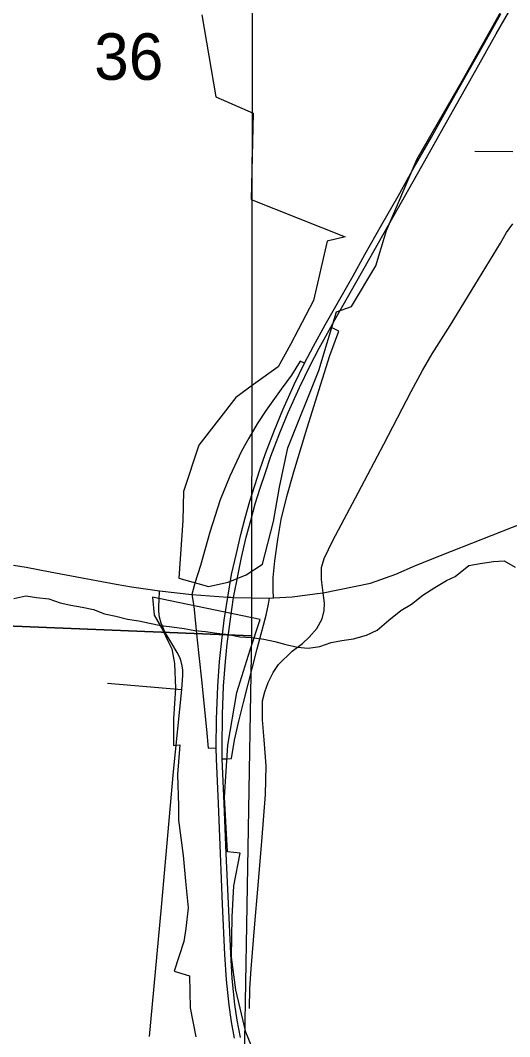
# Model space of a CAD drawing. Extents: x 2.1 to 8.9, y 14.1 to 20.9.
# Drawn here: x 7.249 to 7.689, y 17.687 to 18.602 of the extents above; entities that cross this region are included whole.
import ezdxf

# ---------------------------------------------------------------- set-up
doc = ezdxf.new("R2010")
doc.units = 0
for name, color, linetype in [('GM_X_County_Road_Text', 7, 'Continuous'), ('GM_X_Interchange_Ramps', 7, 'Continuous'), ('GM_X_Rail_Line_Text', 7, 'Continuous'), ('GM_X_State_Shield', 7, 'Continuous'), ('GM_X_Township_Road', 7, 'Continuous'), ('GM_X_Unincorporated', 7, 'Continuous'), ('GM_X_Unincorporated_Text', 7, 'Continuous'), ('TX_P_Misc', 7, 'Continuous')]:
    doc.layers.add(name, color=color, linetype=linetype)

msp = doc.modelspace()

# ---------------------------------------------------------------- linework, layer by layer
at = {"layer": 'GM_X_Interchange_Ramps'}
for p, q in [((7.45846, 19.10807), (7.45701, 18.04776)), ((7.45701, 18.04776), (6.44653, 18.08952)), ((6.44653, 18.08952), (7.45701, 18.04776)), ((7.45701, 18.04776), (7.44097, 17.09977))]:
    msp.add_line(p, q, dxfattribs=at)
at = {"layer": 'GM_X_Rail_Line_Text'}
for p, q in [((7.67745, 18.58945), (7.70305, 18.63467)), ((7.66704, 18.58183), (7.6815, 18.60746)), ((7.65903, 18.55671), (7.67745, 18.58945)), ((7.65216, 18.55536), (7.66704, 18.58183)), ((7.63273, 18.51016), (7.65903, 18.55671)), ((7.63373, 18.52289), (7.65216, 18.55536)), ((7.61896, 18.49652), (7.63373, 18.52289)), ((7.6103, 18.47046), (7.63273, 18.51016)), ((7.60356, 18.46943), (7.61896, 18.49652)), ((7.58426, 18.42437), (7.6103, 18.47046)), ((7.58899, 18.44354), (7.60356, 18.46943)), ((7.57453, 18.41806), (7.58899, 18.44354)), ((7.55834, 18.3785), (7.58426, 18.42437)), ((7.55918, 18.39091), (7.57453, 18.41806)), ((7.54848, 18.37186), (7.55918, 18.39091)), ((7.53219, 18.33221), (7.55834, 18.3785)), ((7.53303, 18.34451), (7.54848, 18.37186)), ((7.52342, 18.32764), (7.53303, 18.34451)), ((7.52849, 18.32567), (7.53219, 18.33221)), ((7.51285, 18.30852), (7.52342, 18.32764)), ((7.51792, 18.30655), (7.52849, 18.32567)), ((7.50488, 18.29304), (7.51285, 18.30852)), ((7.50971, 18.2906), (7.51792, 18.30655)), ((7.49544, 18.27382), (7.50488, 18.29304)), ((7.50027, 18.27138), (7.50971, 18.2906)), ((7.48534, 18.25111), (7.49544, 18.27382)), ((7.49008, 18.24865), (7.50027, 18.27138)), ((7.47779, 18.23274), (7.48534, 18.25111)), ((7.48262, 18.23031), (7.49008, 18.24865)), ((7.46979, 18.21189), (7.47779, 18.23274)), ((7.47462, 18.20946), (7.48262, 18.23031)), ((7.46472, 18.1973), (7.46979, 18.21189)), ((7.46955, 18.19486), (7.47462, 18.20946)), ((7.46006, 18.18305), (7.46472, 18.1973)), ((7.46489, 18.18061), (7.46955, 18.19486)), ((7.45568, 18.16887), (7.46006, 18.18305)), ((7.46051, 18.16643), (7.46489, 18.18061)), ((7.45151, 18.15407), (7.45568, 18.16887)), ((7.45634, 18.15163), (7.46051, 18.16643)), ((7.44755, 18.13898), (7.45151, 18.15407)), ((7.45238, 18.13655), (7.45634, 18.15163)), ((7.44347, 18.1218), (7.44755, 18.13898)), ((7.44819, 18.11837), (7.45238, 18.13655)), ((7.43919, 18.10285), (7.44347, 18.1218)), ((7.44446, 18.10034), (7.44819, 18.11837)), ((7.4357, 18.08267), (7.43919, 18.10285)), ((7.44212, 18.08831), (7.44407, 18.09833)), ((7.44407, 18.09833), (7.44446, 18.10034)), ((7.43248, 18.06179), (7.4357, 18.08267)), ((7.44095, 18.0823), (7.44212, 18.08831)), ((7.43772, 18.06056), (7.44095, 18.0823)), ((7.42993, 18.04075), (7.43248, 18.06179)), ((7.43528, 18.04048), (7.43772, 18.06056)), ((7.42836, 18.02473), (7.42993, 18.04075)), ((7.43362, 18.0247), (7.43528, 18.04048)), ((7.42669, 18.00244), (7.42836, 18.02473)), ((7.43195, 18.00239), (7.43362, 18.0247)), ((7.42549, 17.97289), (7.42669, 18.00244)), ((7.43086, 17.9769), (7.43195, 18.00239)), ((7.42539, 17.94694), (7.42549, 17.97289)), ((7.43064, 17.94707), (7.43086, 17.9769)), ((7.42553, 17.93703), (7.42539, 17.94694)), ((7.43079, 17.93717), (7.43064, 17.94707)), ((7.42732, 17.89689), (7.42553, 17.93703)), ((7.43257, 17.89702), (7.43079, 17.93717)), ((7.42912, 17.85178), (7.42732, 17.89689)), ((7.43438, 17.85191), (7.43257, 17.89702)), ((7.43102, 17.80636), (7.42912, 17.85178)), ((7.43647, 17.80674), (7.43438, 17.85191)), ((7.43311, 17.76089), (7.43102, 17.80636)), ((7.43841, 17.76198), (7.43647, 17.80674)), ((7.43447, 17.73807), (7.43311, 17.76089)), ((7.43973, 17.73939), (7.43841, 17.76198)), ((7.43682, 17.71552), (7.43447, 17.73807)), ((7.4421, 17.71604), (7.43973, 17.73939)), ((7.43901, 17.70038), (7.43682, 17.71552)), ((7.44418, 17.70186), (7.4421, 17.71604)), ((7.44183, 17.68556), (7.43901, 17.70038)), ((7.4471, 17.68629), (7.44418, 17.70186))]:
    msp.add_line(p, q, dxfattribs=at)
at = {"layer": 'GM_X_State_Shield'}
for p, q in [((7.68675, 18.41067), (7.69238, 18.41859)), ((7.68112, 18.40121), (7.68675, 18.41067)), ((7.65797, 18.36327), (7.68112, 18.40121)), ((7.6358, 18.32699), (7.65797, 18.36327)), ((7.61982, 18.30155), (7.6358, 18.32699)), ((7.61113, 18.2866), (7.61982, 18.30155)), ((7.60091, 18.2677), (7.61113, 18.2866)), ((7.5761, 18.22023), (7.60091, 18.2677)), ((7.55323, 18.17658), (7.5761, 18.22023)), ((7.53036, 18.13363), (7.55323, 18.17658)), ((7.63711, 18.12395), (7.71217, 18.15371)), ((7.52237, 18.1175), (7.53036, 18.13363)), ((7.60462, 18.11105), (7.63711, 18.12395)), ((7.24297, 18.11147), (7.25412, 18.10949)), ((7.52008, 18.10916), (7.52237, 18.1175)), ((7.58701, 18.10323), (7.60462, 18.11105)), ((7.25412, 18.10949), (7.27571, 18.1055)), ((7.27571, 18.1055), (7.29975, 18.10101)), ((7.29975, 18.10101), (7.3353, 18.09434)), ((7.51994, 18.09839), (7.52008, 18.10916)), ((7.56408, 18.09525), (7.58701, 18.10323)), ((7.3353, 18.09434), (7.3492, 18.09194)), ((7.3492, 18.09194), (7.3513, 18.09165)), ((7.52161, 18.08644), (7.51994, 18.09839)), ((7.52161, 18.08644), (7.56408, 18.09525)), ((7.3513, 18.09165), (7.3618, 18.09017)), ((7.3618, 18.09017), (7.3744, 18.0884)), ((7.3744, 18.0884), (7.40347, 18.08491)), ((7.40347, 18.08491), (7.4357, 18.08267)), ((7.4357, 18.08267), (7.43832, 18.08248)), ((7.47684, 18.08184), (7.49367, 18.08284)), ((7.49367, 18.08284), (7.51662, 18.08579)), ((7.51662, 18.08579), (7.52161, 18.08644)), ((7.43832, 18.08248), (7.44095, 18.0823)), ((7.44095, 18.0823), (7.47317, 18.08162)), ((7.47317, 18.08162), (7.47684, 18.08184))]:
    msp.add_line(p, q, dxfattribs=at)
at = {"layer": 'GM_X_Township_Road'}
for p, q in [((7.64793, 18.54939), (7.68445, 18.61475)), ((7.41227, 18.60674), (7.42509, 18.53276)), ((7.60633, 18.47702), (7.64793, 18.54939)), ((7.42509, 18.53276), (7.45863, 18.51813)), ((7.45863, 18.51813), (7.45666, 18.44053)), ((7.57848, 18.41269), (7.60633, 18.47702)), ((7.45666, 18.44053), (7.54149, 18.40699)), ((7.56891, 18.38085), (7.57848, 18.41269)), ((7.52522, 18.4028), (7.51289, 18.34953)), ((7.54149, 18.40699), (7.52522, 18.4028)), ((7.54699, 18.34405), (7.56891, 18.38085)), ((7.51289, 18.34953), (7.49217, 18.31008)), ((7.51779, 18.28651), (7.5335, 18.33944)), ((7.5335, 18.33944), (7.54699, 18.34405)), ((7.49217, 18.31008), (7.48107, 18.28986)), ((7.48107, 18.28986), (7.45888, 18.27383)), ((7.48974, 18.21683), (7.51779, 18.28651)), ((7.45888, 18.27383), (7.44285, 18.26224)), ((7.44285, 18.26224), (7.40956, 18.21933)), ((7.40956, 18.21933), (7.39575, 18.17765)), ((7.48216, 18.18164), (7.48974, 18.21683)), ((7.39575, 18.17765), (7.39514, 18.15144)), ((7.47673, 18.15068), (7.48216, 18.18164)), ((7.39514, 18.15144), (7.3917, 18.09977)), ((7.46698, 18.11237), (7.47673, 18.15068)), ((7.45213, 18.10277), (7.46698, 18.11237)), ((7.43605, 18.09617), (7.45213, 18.10277)), ((7.3917, 18.09977), (7.41836, 18.09217)), ((7.41836, 18.09217), (7.43605, 18.09617)), ((7.46482, 18.06252), (7.36788, 18.08256)), ((7.36788, 18.08256), (7.36955, 18.06628)), ((7.36955, 18.06628), (7.37718, 18.05284)), ((7.45585, 18.03524), (7.46482, 18.06252)), ((7.37718, 18.05284), (7.38206, 18.04274)), ((7.38206, 18.04274), (7.38532, 18.036)), ((7.38532, 18.036), (7.38764, 18.02278)), ((7.44383, 17.99685), (7.45585, 18.03524)), ((7.38764, 18.02278), (7.38874, 18.00077)), ((7.38874, 18.00077), (7.38698, 17.97296)), ((7.43589, 17.94946), (7.44383, 17.99685)), ((7.38698, 17.97296), (7.387, 17.94902)), ((7.387, 17.94902), (7.39267, 17.94959)), ((7.39267, 17.94959), (7.3905, 17.92291)), ((7.43286, 17.90261), (7.43589, 17.94946)), ((7.3905, 17.92291), (7.39141, 17.89481)), ((7.43559, 17.85329), (7.43286, 17.90261)), ((7.39141, 17.89481), (7.39145, 17.88188)), ((7.39145, 17.88188), (7.39551, 17.85009)), ((7.39551, 17.85009), (7.39778, 17.82697)), ((7.44701, 17.85213), (7.43559, 17.85329)), ((7.44114, 17.82267), (7.44701, 17.85213)), ((7.39778, 17.82697), (7.40007, 17.80309)), ((7.43976, 17.79487), (7.44114, 17.82267)), ((7.40007, 17.80309), (7.39802, 17.7844)), ((7.43903, 17.75873), (7.43976, 17.79487)), ((7.39802, 17.7844), (7.39612, 17.77255)), ((7.39612, 17.77255), (7.38751, 17.74603)), ((7.44302, 17.7292), (7.43903, 17.75873)), ((7.38751, 17.74603), (7.40129, 17.74192)), ((7.40129, 17.74192), (7.40184, 17.71304)), ((7.45183, 17.69108), (7.44302, 17.7292)), ((7.40184, 17.71304), (7.40685, 17.68696)), ((7.4658, 17.65731), (7.45183, 17.69108))]:
    msp.add_line(p, q, dxfattribs=at)
at = {"layer": 'GM_X_Unincorporated'}
for p, q in [((7.52752, 18.30016), (7.53558, 18.32191)), ((7.53558, 18.32191), (7.52849, 18.32567)), ((7.50087, 18.29503), (7.49297, 18.28243)), ((7.50488, 18.29304), (7.50087, 18.29503)), ((7.51758, 18.26853), (7.52752, 18.30016)), ((7.49297, 18.28243), (7.4838, 18.26965)), ((7.4838, 18.26965), (7.47038, 18.25088)), ((7.50611, 18.23114), (7.51758, 18.26853)), ((7.47038, 18.25088), (7.46232, 18.23851)), ((7.46232, 18.23851), (7.45454, 18.22565)), ((7.49527, 18.19535), (7.50611, 18.23114)), ((7.45454, 18.22565), (7.44821, 18.2139)), ((7.44821, 18.2139), (7.43744, 18.19159)), ((7.48873, 18.17331), (7.49527, 18.19535)), ((7.43744, 18.19159), (7.42882, 18.17005)), ((7.42882, 18.17005), (7.41951, 18.14106)), ((7.48366, 18.15239), (7.48873, 18.17331)), ((7.48067, 18.13446), (7.48366, 18.15239)), ((7.41951, 18.14106), (7.4111, 18.11118)), ((7.47803, 18.11535), (7.48067, 18.13446)), ((7.4111, 18.11118), (7.40615, 18.09508)), ((7.47671, 18.10013), (7.47803, 18.11535)), ((7.40582, 18.09401), (7.40347, 18.08491)), ((7.40615, 18.09508), (7.40582, 18.09401)), ((7.47664, 18.08887), (7.47671, 18.10013)), ((7.40347, 18.08491), (7.40526, 18.07448)), ((7.47684, 18.08184), (7.47664, 18.08887)), ((7.40526, 18.07448), (7.40797, 18.04668)), ((7.47018, 18.06633), (7.47233, 18.07619)), ((7.47233, 18.07619), (7.47317, 18.08162)), ((7.46225, 18.0361), (7.47018, 18.06633)), ((7.40797, 18.04668), (7.412, 18.00831)), ((7.44988, 17.98786), (7.46225, 18.0361)), ((7.412, 18.00831), (7.41652, 17.96362)), ((7.44557, 17.97111), (7.44988, 17.98786)), ((7.44175, 17.95388), (7.44557, 17.97111)), ((7.41652, 17.96362), (7.41806, 17.94676)), ((7.41806, 17.94676), (7.42539, 17.94694)), ((7.43918, 17.93726), (7.44175, 17.95388)), ((7.43079, 17.93717), (7.43558, 17.93722)), ((7.43558, 17.93722), (7.43918, 17.93726))]:
    msp.add_line(p, q, dxfattribs=at)
at = {"layer": 'GM_X_Unincorporated_Text'}
for p, q in [((7.65804, 18.48401), (7.69219, 18.48375)), ((7.37388, 18.07982), (7.3744, 18.0884)), ((7.52272, 18.07726), (7.52161, 18.08644)), ((7.37353, 18.07474), (7.37388, 18.07982)), ((7.37367, 18.06998), (7.37353, 18.07474)), ((7.52241, 18.07064), (7.52272, 18.07726)), ((7.37433, 18.06466), (7.37367, 18.06998)), ((7.37582, 18.0591), (7.37433, 18.06466)), ((7.52056, 18.06308), (7.52241, 18.07064)), ((7.37815, 18.05337), (7.37582, 18.0591)), ((7.51577, 18.05426), (7.52056, 18.06308)), ((7.38027, 18.04916), (7.37815, 18.05337)), ((7.38528, 18.041), (7.38027, 18.04916)), ((7.50283, 18.04079), (7.5091, 18.04668)), ((7.5091, 18.04668), (7.51577, 18.05426)), ((7.39028, 18.0328), (7.38528, 18.041)), ((7.49356, 18.03391), (7.50283, 18.04079)), ((7.39254, 18.02828), (7.39028, 18.0328)), ((7.39383, 18.02459), (7.39254, 18.02828)), ((7.48137, 18.02187), (7.49356, 18.03391)), ((7.39476, 18.02074), (7.39383, 18.02459)), ((7.39529, 18.01681), (7.39476, 18.02074)), ((7.4765, 18.01471), (7.48137, 18.02187)), ((7.39445, 17.99961), (7.39532, 18.01226)), ((7.39532, 18.01226), (7.39529, 18.01681)), ((7.47198, 18.00574), (7.4765, 18.01471)), ((7.32732, 18.0053), (7.39445, 17.99961)), ((7.46906, 17.99747), (7.47198, 18.00574)), ((7.38696, 17.92561), (7.39445, 17.99961)), ((7.46712, 17.98913), (7.46906, 17.99747)), ((7.46712, 17.97231), (7.46712, 17.98913)), ((7.46851, 17.95417), (7.46712, 17.97231)), ((7.4702, 17.93073), (7.46851, 17.95417)), ((7.4697, 17.90488), (7.4702, 17.93073)), ((7.3761, 17.80347), (7.38696, 17.92561)), ((7.4683, 17.88571), (7.4697, 17.90488)), ((7.46635, 17.86264), (7.4683, 17.88571)), ((7.46281, 17.81975), (7.46635, 17.86264)), ((7.46017, 17.78848), (7.46281, 17.81975)), ((7.36512, 17.68712), (7.3761, 17.80347)), ((7.45676, 17.74802), (7.46017, 17.78848)), ((7.45558, 17.72995), (7.45676, 17.74802)), ((7.45529, 17.71248), (7.45558, 17.72995))]:
    msp.add_line(p, q, dxfattribs=at)
at = {"layer": 'TX_P_Misc'}
for p, q in [((7.64055, 18.10113), (7.65262, 18.11106)), ((7.65262, 18.11106), (7.66283, 18.11286)), ((7.66283, 18.11286), (7.67494, 18.11471)), ((7.67494, 18.11471), (7.68442, 18.11535)), ((7.68442, 18.11535), (7.69446, 18.10953)), ((7.63246, 18.09757), (7.64055, 18.10113)), ((7.62199, 18.0912), (7.63246, 18.09757)), ((7.24299, 18.08133), (7.25394, 18.08391)), ((7.25394, 18.08391), (7.26349, 18.08226)), ((7.60111, 18.07617), (7.61115, 18.08443)), ((7.61115, 18.08443), (7.62199, 18.0912)), ((7.26349, 18.08226), (7.27454, 18.08104)), ((7.27454, 18.08104), (7.2849, 18.07751)), ((7.2849, 18.07751), (7.29445, 18.07549)), ((7.29445, 18.07549), (7.30477, 18.07348)), ((7.30477, 18.07348), (7.3147, 18.07147)), ((7.59138, 18.07057), (7.60111, 18.07617)), ((7.3147, 18.07147), (7.32469, 18.06755)), ((7.32469, 18.06755), (7.335, 18.06554)), ((7.335, 18.06554), (7.34534, 18.06278)), ((7.58059, 18.06191), (7.59138, 18.07057)), ((7.34534, 18.06278), (7.35564, 18.06115)), ((7.35564, 18.06115), (7.3652, 18.05913)), ((7.3652, 18.05913), (7.37551, 18.05712)), ((7.37551, 18.05712), (7.38542, 18.05587)), ((7.38542, 18.05587), (7.39649, 18.05426)), ((7.5702, 18.05287), (7.58059, 18.06191)), ((7.39649, 18.05426), (7.40603, 18.05262)), ((7.40603, 18.05262), (7.41556, 18.05173)), ((7.41556, 18.05173), (7.42586, 18.05011)), ((7.42586, 18.05011), (7.43654, 18.04888)), ((7.43654, 18.04888), (7.44647, 18.04686)), ((7.44647, 18.04686), (7.45712, 18.04639)), ((7.45712, 18.04639), (7.46819, 18.04478)), ((7.54874, 18.04506), (7.56044, 18.04842)), ((7.56044, 18.04842), (7.5702, 18.05287)), ((7.46819, 18.04478), (7.47812, 18.04277)), ((7.47812, 18.04277), (7.48808, 18.03999)), ((7.48808, 18.03999), (7.4984, 18.0376)), ((7.4984, 18.0376), (7.50793, 18.03672)), ((7.50793, 18.03672), (7.51853, 18.03815)), ((7.51853, 18.03815), (7.52869, 18.04185)), ((7.52869, 18.04185), (7.53852, 18.04364)), ((7.53852, 18.04364), (7.54874, 18.04506))]:
    msp.add_line(p, q, dxfattribs=at)

# ---------------------------------------------------------------- texts
at = {"layer": 'GM_X_County_Road_Text'}
msp.add_text('36', height=0.041856, rotation=0.00001, dxfattribs=at).set_placement((7.31546, 18.54814))

doc.saveas('drawing.dxf')
